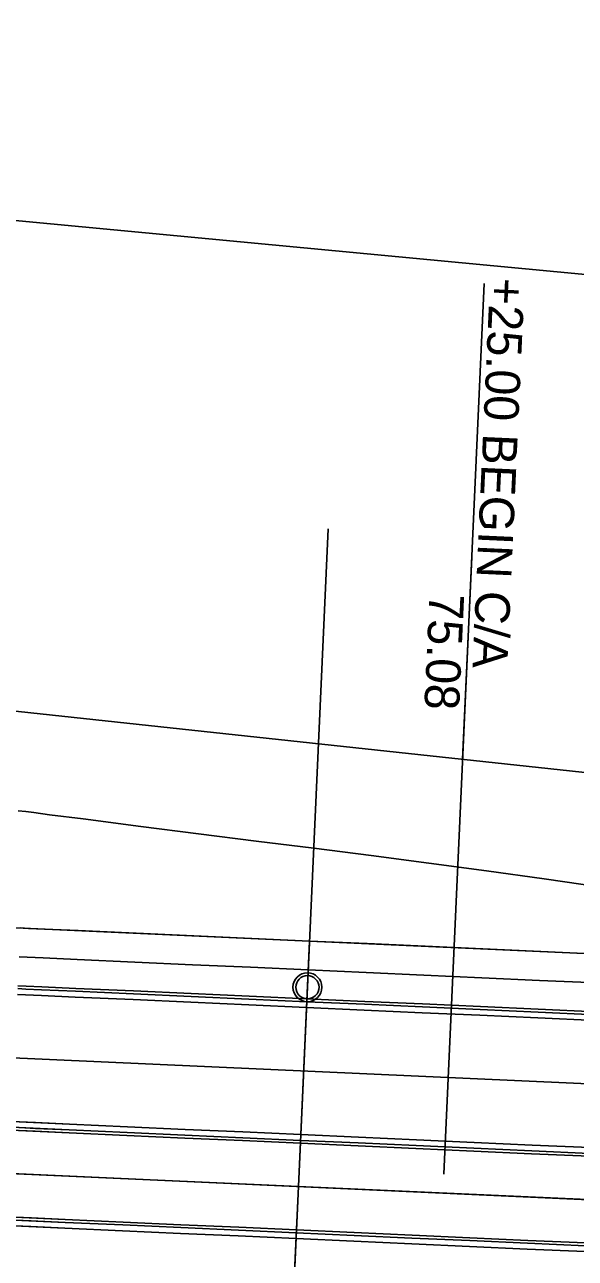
# Model space of a CAD drawing. Extents: x -70 to 701944, y -4 to 666871.
# Drawn here: x 666595.9 to 666691, y 656596.1 to 656809.4 of the extents above; entities that cross this region are included whole.
import ezdxf

# ---------------------------------------------------------------- set-up
doc = ezdxf.new("R2010")
doc.units = 0
for name, color, linetype in [('R_Detour', 7, 'Continuous'), ('R_Horz Alg', 7, 'Continuous'), ('R_No Plot', 7, 'Continuous'), ('R_Proposed Const Limits', 7, 'Continuous'), ('R_Proposed Road', 7, 'Continuous'), ('R_ROW', 7, 'Continuous'), ('R_ROW Annot', 7, 'Continuous'), ('R_Striping', 7, 'Continuous'), ('R_Water', 7, 'Continuous')]:
    doc.layers.add(name, color=color, linetype=linetype)

msp = doc.modelspace()

# ---------------------------------------------------------------- linework, layer by layer
at = {"layer": 'R_Detour'}
for p in [(666648.32, 656722.23), (666638.85, 656512.52)]:
    msp.add_line(p, (666643.18, 656608.51), dxfattribs=at)
msp.add_lwpolyline([(666752.36, 656760.54), (665316.65, 656896.69), (665390.15, 656859.14)], dxfattribs=at)
at = {"layer": 'R_Horz Alg'}
msp.add_line((667725.26, 656559.62), (664961.47, 656684.5), dxfattribs=at)
at = {"layer": 'R_No Plot'}
for p, q in [((666675.26, 656764.64), (666668.31, 656610.66)), ((667813.84, 656555.62), (664810.54, 656691.32)), ((667725.26, 656559.62), (664961.47, 656684.5))]:
    msp.add_line(p, q, dxfattribs=at)
for points in [[(666495.25, 656657.74), (666645.1, 656650.97), (666643.18, 656608.51), (666493.34, 656615.28)], [(666745.12, 656649.12), (666700.35, 656648.47), (666645.1, 656650.97), (666643.18, 656608.51), (666693.13, 656606.26), (666743.25, 656608.73)], [(666493.34, 656615.28), (666643.18, 656608.51), (666640.72, 656554.07), (666579.66, 656556.15), (666531.47, 656547.34), (666506.44, 656543.07), (666490.05, 656542.43)], [(666643.18, 656608.51), (666640.72, 656554.07), (666740.56, 656548.21), (666743.3, 656608.73), (666693.13, 656606.26)]]:
    msp.add_lwpolyline(points, close=True, dxfattribs=at)
msp.add_circle((666644.74, 656642.98), 2.5, dxfattribs=at)
at = {"layer": 'R_Proposed Const Limits'}
msp.add_lwpolyline([(666695.57, 656660.29), (666685.63, 656661.7), (666675.68, 656663.12), (666665.73, 656664.43), (666655.78, 656665.77), (666645.83, 656667.05), (666635.87, 656668.25), (666625.92, 656669.51), (666615.97, 656670.79), (666606.01, 656672.07), (666600.18, 656672.81), (666597.46, 656673.19), (666596.06, 656673.35), (666594.75, 656673.5)], dxfattribs=at)
at = {"layer": 'R_Proposed Road'}
for points in [[(666695.05, 656648.71), (666685.06, 656649.16), (666675.07, 656649.61), (666665.08, 656650.07), (666655.09, 656650.52), (666645.1, 656650.97), (666635.11, 656651.42), (666625.12, 656651.87), (666615.13, 656652.32), (666605.14, 656652.77), (666599.28, 656653.04), (666596.56, 656653.16), (666595.15, 656653.23)], [(666694.83, 656643.72), (666684.84, 656644.17), (666674.85, 656644.62), (666664.86, 656645.07), (666654.87, 656645.52), (666644.88, 656645.97), (666634.89, 656646.42), (666624.9, 656646.88), (666614.91, 656647.33), (666604.92, 656647.78), (666599.06, 656648.04), (666596.33, 656648.17), (666594.93, 656648.23)], [(666694.53, 656637.22), (666684.54, 656637.67), (666674.55, 656638.13), (666664.56, 656638.58), (666654.57, 656639.03), (666644.58, 656639.48), (666634.59, 656639.93), (666624.6, 656640.38), (666614.61, 656640.83), (666604.62, 656641.29), (666598.76, 656641.55), (666596.04, 656641.67), (666594.63, 656641.74)], [(666694.58, 656638.22), (666684.59, 656638.67), (666674.6, 656639.13), (666664.61, 656639.58), (666654.62, 656640.03), (666644.63, 656640.48), (666634.64, 656640.93), (666624.65, 656641.38), (666614.66, 656641.83), (666604.67, 656642.28), (666598.81, 656642.55), (666596.09, 656642.67), (666594.68, 656642.74)], [(666694.6, 656638.72), (666684.61, 656639.17), (666674.62, 656639.62), (666664.63, 656640.08), (666654.64, 656640.53), (666644.65, 656640.98), (666634.66, 656641.43), (666624.67, 656641.88), (666614.68, 656642.33), (666604.69, 656642.78), (666598.83, 656643.05), (666596.11, 656643.17), (666594.7, 656643.24)], [(666693.47, 656613.75), (666683.48, 656614.2), (666673.49, 656614.65), (666663.5, 656615.1), (666653.51, 656615.55), (666643.52, 656616), (666633.53, 656616.46), (666623.54, 656616.91), (666613.55, 656617.36), (666603.56, 656617.81), (666593.57, 656618.26)], [(666693.49, 656614.25), (666683.5, 656614.7), (666673.51, 656615.15), (666663.52, 656615.6), (666653.53, 656616.05), (666643.54, 656616.5), (666633.55, 656616.96), (666623.57, 656617.41), (666613.58, 656617.86), (666603.59, 656618.31), (666593.6, 656618.76)], [(666693.54, 656615.25), (666683.55, 656615.7), (666673.56, 656616.15), (666663.57, 656616.6), (666653.58, 656617.05), (666643.59, 656617.5), (666633.6, 656617.95), (666623.61, 656618.41), (666613.62, 656618.86), (666603.63, 656619.31), (666593.64, 656619.76)], [(666693.47, 656613.75), (666683.48, 656614.2), (666673.49, 656614.65), (666663.5, 656615.1), (666653.51, 656615.55), (666643.52, 656616), (666633.53, 656616.46), (666623.54, 656616.91), (666613.55, 656617.36), (666603.56, 656617.81), (666597.7, 656618.07), (666594.98, 656618.2)], [(666693.49, 656614.25), (666683.5, 656614.7), (666673.51, 656615.15), (666663.52, 656615.6), (666653.53, 656616.05), (666643.54, 656616.5), (666633.55, 656616.96), (666623.57, 656617.41), (666613.58, 656617.86), (666603.59, 656618.31), (666597.73, 656618.57), (666595, 656618.7)], [(666693.54, 656615.25), (666683.55, 656615.7), (666673.56, 656616.15), (666663.57, 656616.6), (666653.58, 656617.05), (666643.59, 656617.5), (666633.6, 656617.95), (666623.61, 656618.41), (666613.62, 656618.86), (666603.63, 656619.31), (666597.77, 656619.57), (666595.05, 656619.7)], [(666692.79, 656598.76), (666682.8, 656599.21), (666672.81, 656599.67), (666662.82, 656600.12), (666652.83, 656600.57), (666642.85, 656601.02), (666632.86, 656601.47), (666622.87, 656601.92), (666612.88, 656602.37), (666602.89, 656602.82), (666592.9, 656603.28)], [(666692.79, 656598.76), (666682.8, 656599.21), (666672.81, 656599.67), (666662.82, 656600.12), (666652.83, 656600.57), (666642.85, 656601.02), (666632.86, 656601.47), (666622.87, 656601.92), (666612.88, 656602.37), (666602.89, 656602.82), (666597.03, 656603.09), (666594.3, 656603.21)], [(666692.73, 656597.26), (666682.74, 656597.72), (666672.75, 656598.17), (666662.76, 656598.62), (666652.77, 656599.07), (666642.78, 656599.52), (666632.79, 656599.97), (666622.8, 656600.42), (666612.81, 656600.88), (666602.82, 656601.33), (666592.83, 656601.78)], [(666692.77, 656598.26), (666682.78, 656598.71), (666672.79, 656599.17), (666662.8, 656599.62), (666652.81, 656600.07), (666642.82, 656600.52), (666632.83, 656600.97), (666622.84, 656601.42), (666612.85, 656601.87), (666602.86, 656602.33), (666592.87, 656602.78)], [(666692.73, 656597.26), (666682.74, 656597.72), (666672.75, 656598.17), (666662.76, 656598.62), (666652.77, 656599.07), (666642.78, 656599.52), (666632.79, 656599.97), (666622.8, 656600.42), (666612.81, 656600.88), (666602.82, 656601.33), (666596.96, 656601.59), (666594.23, 656601.71)], [(666692.77, 656598.26), (666682.78, 656598.71), (666672.79, 656599.17), (666662.8, 656599.62), (666652.81, 656600.07), (666642.82, 656600.52), (666632.83, 656600.97), (666622.84, 656601.42), (666612.85, 656601.87), (666602.86, 656602.33), (666597, 656602.59), (666594.28, 656602.71)]]:
    msp.add_lwpolyline(points, dxfattribs=at)
at = {"layer": 'R_ROW'}
msp.add_lwpolyline([(668183.45, 656677.29), (668041.7, 656619.63), (667513.59, 656642.26), (667480, 656629.76), (667392.27, 656637.73), (667276.83, 656674.98), (667204.95, 656679.23), (667093.98, 656660.22), (667018.55, 656674.64), (666944.63, 656677.98), (666832.93, 656665.01), (666352.77, 656716.73), (665777.5, 656723.7), (665727.42, 656722.96), (665452.7, 656735.37), (665090.34, 656757.75), (665090.29, 656778.78), (664696.26, 656796.57), (664695.54, 656784.55), (664566.62, 656799.96)], dxfattribs=at)
at = {"layer": 'R_ROW Annot'}
msp.add_lwpolyline([(666671.55, 656682.39), (666673.13, 656717.35)], dxfattribs=at)
at = {"layer": 'R_Striping'}
msp.add_lwpolyline([(666699.66, 656625.98), (666096.29, 656653.24), (665996.53, 656660.75), (665796.9, 656669.77)], dxfattribs=at)
at = {"layer": 'R_Water'}
msp.add_circle((666644.74, 656642.98), 2, dxfattribs=at)

# ---------------------------------------------------------------- texts
at = {"layer": 'R_ROW Annot'}
for s, p in [('+25.00 BEGIN C/A', (666676.31, 656765.74)), ('75.08', (666665.84, 656711.13))]:
    msp.add_text(s, height=6, rotation=267.4131, dxfattribs=at).set_placement(p)

doc.saveas('drawing.dxf')
